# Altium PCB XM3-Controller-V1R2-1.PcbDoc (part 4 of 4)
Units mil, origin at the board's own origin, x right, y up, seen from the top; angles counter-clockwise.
Board outline 10629.92 x 4173.11 mil, 6 copper layers (TOP, GND1, LAYER3, PWR, GND2, BOTTOM), stack 62 mil thick; 362 components, 276 nets, 1145 pads, 503 vias.
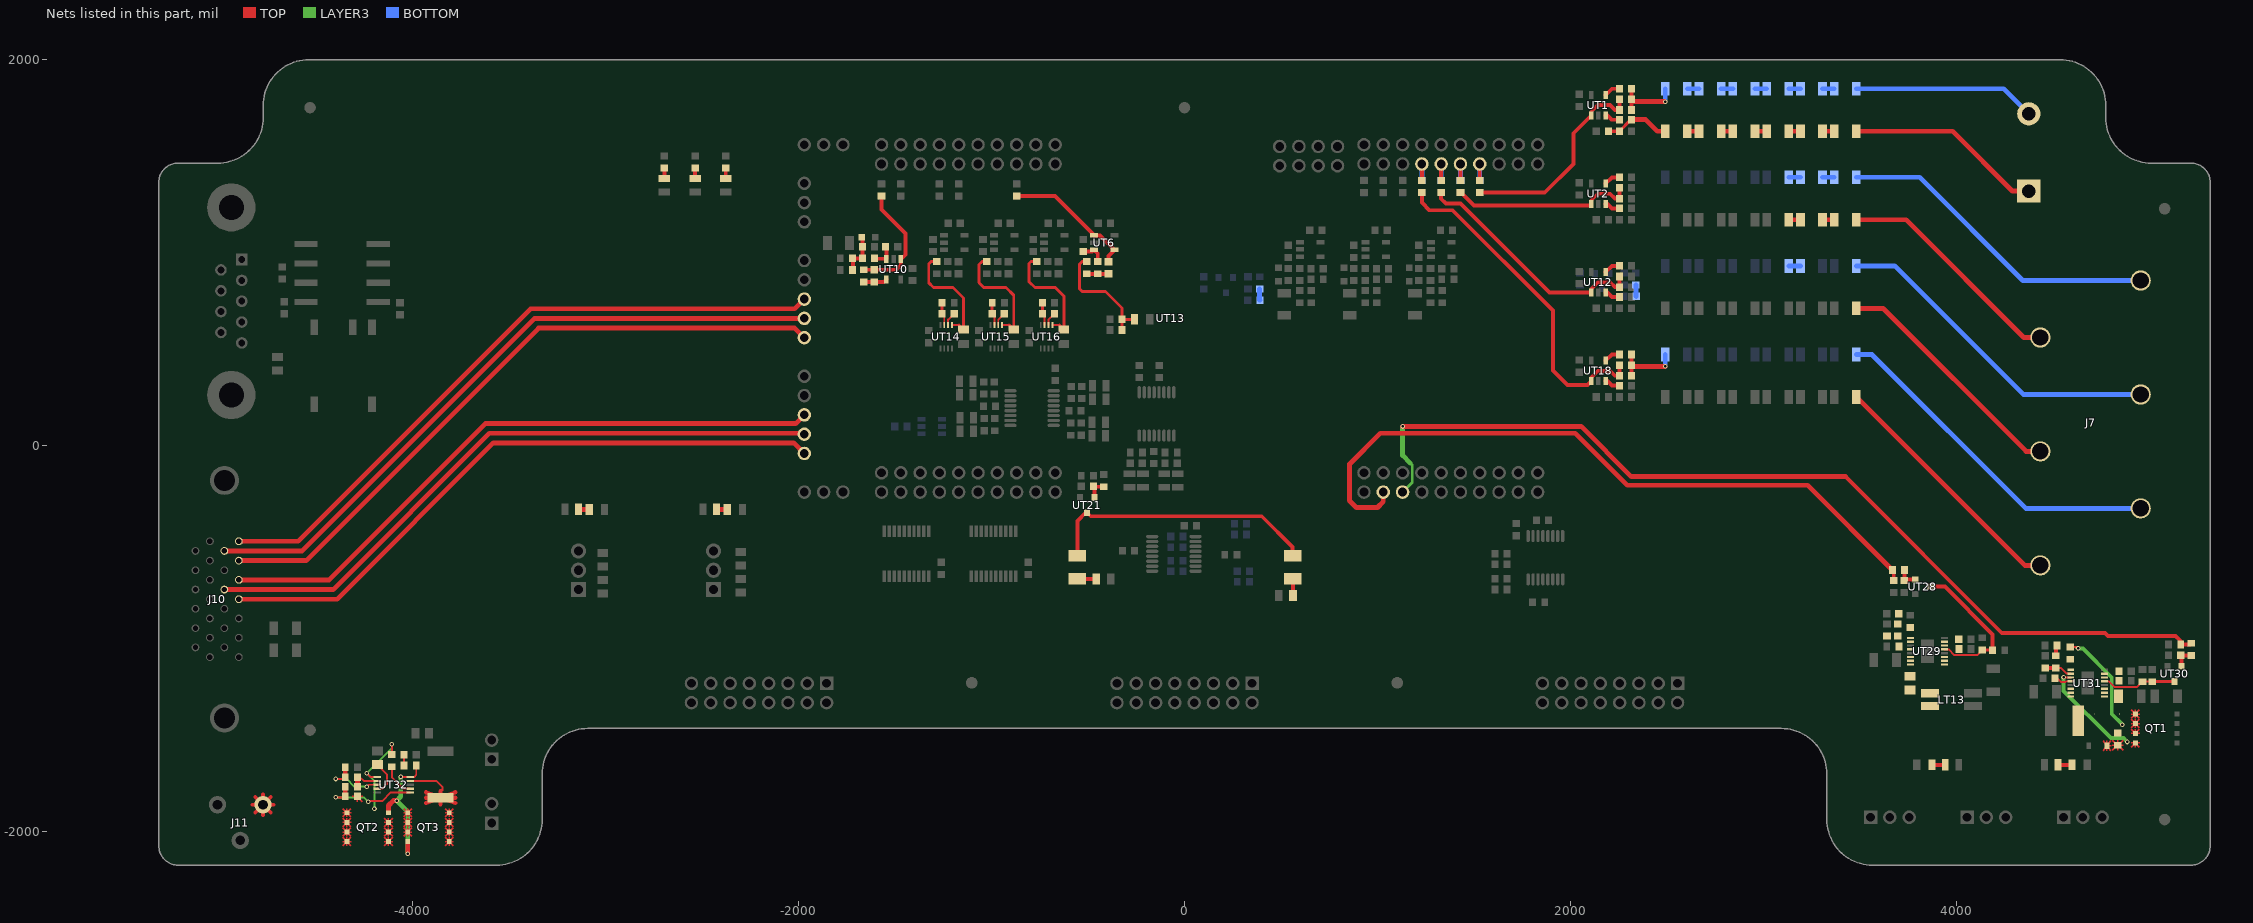
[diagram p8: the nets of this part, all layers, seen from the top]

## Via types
v1: diameter 24, hole 13, TOP to BOTTOM, 503 vias

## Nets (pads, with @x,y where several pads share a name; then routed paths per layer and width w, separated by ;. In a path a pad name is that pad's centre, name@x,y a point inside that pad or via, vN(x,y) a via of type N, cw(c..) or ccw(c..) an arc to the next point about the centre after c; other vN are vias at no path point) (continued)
N51250: RB14.2 RB15.1 | length 60.8
  BOTTOM w25: RB15.1@3130.68,931.88 RB14.2@3191.5,931.88
N51378: RT34.1 RT35.2 | length 60.8
  TOP w25: RT34.1@3305.68,1170.94 RT35.2@3366.5,1170.94
N51382: RT33.1 RT34.2 | length 60.8
  TOP w25: RT33.1@3130.68,1170.94 RT34.2@3191.5,1170.94
N51422: RB7.2 RB8.1 | length 60.8
  BOTTOM w25: RB8.1@3305.68,1390.94 RB7.2@3366.5,1390.94
N51426: RB8.2 RB9.1 | length 60.8
  BOTTOM w25: RB9.1@3130.68,1390.94 RB8.2@3191.5,1390.94
N62914: CT14.1 RT37.2 RT38.2 RT39.1 RT49.2 | length 226.3
  TOP w20: RT49.2@-1721,910.64 -1717.5,914.14 -1717.5,967.14 RT38.2@-1721,970.64 RT39.1@-1669,970.64 RT37.2@-1669,1030.64 -1669,1077.14 CT14.1@-1672.5,1080.64
N63160: CT19.1 RT39.2 UT10.3 | length 125.4
  TOP w20: RT39.2@-1606,970.64 -1604.15,968.79 UT10.3@-1544.9,968.79 -1544.9,1026.54 CT19.1@-1549,1030.64
N63220: CT34.2 RT23.1 RT57.2 UT10.1 | length 625.9
  TOP w20: RT57.2@-1662.5,912.14 CT34.2@-1607.5,912.14 -1491.48,912.14 -1470.1,933.52 UT10.1@-1470.1,968.79 -1466.21,968.79 -1445,990 -1445,1100 -1570,1225 RT23.1@-1570,1293.72
N63260: CT34.1 RT57.1 UT10.4 | length 123.1
  TOP w20: RT57.1@-1662.5,849.14 CT34.1@-1607.5,849.14 -1558.25,849.14 UT10.4@-1544.9,862.49
N66752: CT51.2 RT18.1 RT88.2 UT18.1 | length 1755.3
  TOP w20: RT18.1@1230,1312 1230,1260 1270,1220 1390,1220 1910,700 1910,390 1985,315 2087.93,315 UT18.1@2107.6,334.67 2107.6,353.8 2141.62,387.82 2205,387.82 2230,362.82 CT51.2@2253.5,362.82 RT88.2@2253.5,417.82
N66907: CT51.1 RB26.2 RT87.1 RT88.1 | length 348.9
  TOP w20: CT51.1@2316.5,362.82 RT88.1@2316.5,417.82 RT87.1@2316.5,472.82
  TOP w25: RT88.1@2316.5,417.82 2322.82,411.5 v1(2491.5,411.5)
  BOTTOM w25: v1(2491.5,411.5) RB26.2@2491.5,472.82
N66989: RT87.2 UT18.4 | length 84.3
  TOP w20: UT18.4@2182.4,440.97 2214.25,472.82 RT87.2@2253.5,472.82
N67029: RT90.2 UT18.3 | length 80.6
  TOP w20: UT18.3@2182.4,334.67 2193.14,334.67 2216.05,311.76 RT90.2@2253.5,311.76
N74358: RT68.2 UT12.3 | length 80.6
  TOP w20: UT12.3@2182.4,793.73 2193.14,793.73 2216.05,770.82 RT68.2@2253.5,770.82
N74448: CT36.2 RT19.1 RT58.2 UT12.1 | length 1255.5
  TOP w20: RT19.1@1330,1312 1330,1280 1355,1255 1430,1255 1891.27,793.73 UT12.1@2107.6,793.73 2107.6,812.86 2141.62,846.88 2205,846.88 2230,821.88 CT36.2@2253.5,821.88 RT58.2@2253.5,876.88
N74460: RT40.2 UT12.4 | length 84.3
  TOP w20: UT12.4@2182.4,900.03 2214.25,931.88 RT40.2@2253.5,931.88
N75234: RT28.2 UT2.3 | length 80.6
  TOP w20: UT2.3@2182.4,1252.79 2193.14,1252.79 2216.05,1229.88 RT28.2@2253.5,1229.88
N75324: CT5.2 RT20.1 RT22.2 UT2.1 | length 953.1
  TOP w20: RT20.1@1430,1312 1433,1312 1500,1245 2099.81,1245 UT2.1@2107.6,1252.79 2107.6,1271.92 2141.62,1305.94 2205,1305.94 2230,1280.94 CT5.2@2253.5,1280.94 RT22.2@2253.5,1335.94
N75336: RT14.2 UT2.4 | length 84.3
  TOP w20: UT2.4@2182.4,1359.09 2214.25,1390.94 RT14.2@2253.5,1390.94
N76078: CT3.2 RT3.1 RT4.2 RT5.2 | length 344.7
  TOP w15: RT4.2@2253.5,1630 2312.44,1688.94 RT3.1@2316.5,1688.94
  TOP w20: CT3.2@2196.5,1630 RT4.2@2253.5,1630
  TOP w25: RT3.1@2316.5,1688.94 2317.56,1690 2390,1690 2450,1630 RT5.2@2491.5,1630
N76134: RT3.2 UT1.3 | length 80.6
  TOP w20: UT1.3@2182.4,1711.85 2193.14,1711.85 2216.05,1688.94 RT3.2@2253.5,1688.94
N76224: CT2.2 RT2.2 RT21.1 UT1.1 | length 1081
  TOP w20: RT21.1@1530,1312 1866.99,1312 2015,1460.01 2015,1619.25 UT1.1@2107.6,1711.85 2107.6,1730.98 2141.62,1765 2205,1765 2230,1740 CT2.2@2253.5,1740 RT2.2@2253.5,1795
N76236: RT1.2 UT1.4 | length 84.3
  TOP w20: UT1.4@2182.4,1818.15 2214.25,1850 RT1.2@2253.5,1850
N76260: CT2.1 RB6.2 RT1.1 RT2.1 | length 356.3
  TOP w20: CT2.1@2316.5,1740 RT2.1@2316.5,1795 RT1.1@2316.5,1850
  TOP w25: RT2.1@2316.5,1795 2328,1783.5 v1(2491.5,1783.5)
  BOTTOM w25: v1(2491.5,1783.5) RB6.2@2491.5,1850
N78650: CT26.1 RT47.2 RT48.1 | length 111.9
  TOP w20: RT47.2@-505.61,890.9 RT48.1@-449.67,890.9 CT26.1@-393.73,890.9
N78658: CT26.2 RT27.1 UT6.1 UT6.4 | length 698.1
  TOP w20: RT27.1@-870,1293.72 -670.91,1293.72 -468.76,1091.57 UT6.1@-468.76,1089.8 -437.26,1089.8 UT6.4@-362.46,1015 -393.73,983.73 CT26.2@-393.73,953.9
N78724: CT18.2 RT48.2 UT6.3 | length 129.6
  TOP w20: CT18.2@-525.61,1005.9 -477.86,1005.9 UT6.3@-468.76,1015 -449.67,995.91 RT48.2@-449.67,953.9
N79088: CT43.2 RT47.1 RT82.2 RT83.1 | length 612.2
  TOP w15: RT47.1@-505.61,953.9 -506.71,955 -530,955 -545,940 -545,815 -530,800 -410,800 -323.5,713.5 RT82.2@-323.5,655 ; CT43.2@-323.5,600 RT82.2@-323.5,655 ; RT83.1@-259.37,655 RT82.2@-323.5,655
N88263: DT5.1 RT110.2 | length 55.6
  TOP w25: DT5.1@-2425,-330 RT110.2@-2369.37,-330
N88433: DT4.1 RT109.2 | length 55.6
  TOP w25: DT4.1@-3140,-330 RT109.2@-3084.37,-330
N88603: DT12.1 RT138.2 | length 73
  TOP w20: DT12.1@4526,-1653.47 RT138.2@4599.01,-1653.47
N88777: DT11.1 RT137.2 | length 68.4
  TOP w20: RT137.2@3873.59,-1653.47 DT11.1@3942,-1653.47
N93191: DT1.1 RT11.2 | length 53.5
  TOP w20: DT1.1@-2695,1385 RT11.2@-2695,1438.5
N93195: DT3.1 RT13.2 | length 53.5
  TOP w20: DT3.1@-2376.88,1385 RT13.2@-2376.88,1438.5
N93199: DT2.1 RT12.2 | length 53.5
  TOP w20: DT2.1@-2535.94,1385 RT12.2@-2535.94,1438.5
N95779: RT123.1 RT128.1 UT28.3 UT29.13 | length 779.1
  TOP w10: UT29.13@3938,-1055.15 3958.9,-1055.15 3988.44,-1084.69 4106.81,-1084.69 RT123.1@4134,-1057.5
  TOP w15: RT123.1@4134,-1057.5 4186,-1057.5 RT128.1@4187.5,-1059
  TOP w20: UT28.3@3866,-730 3940.01,-730 4187.5,-977.49 RT128.1@4187.5,-1059
N96795: RT131.1 RT132.1 UT30.3 UT31.13 | length 386.1
  TOP w10: UT31.13@4768,-1220.15 4788.9,-1220.15 4818.44,-1249.69 4936.81,-1249.69 RT131.1@4964,-1222.5 RT132.1@5014,-1222.5
  TOP w15: RT132.1@5014,-1222.5 5128.5,-1222.5 UT30.3@5130,-1221
N97055: CT84.1 DT9.1 QT1.1 QT1.2 QT1.3 RT129.2 RT135.1 | length 1089.1
  TOP w7: 4905.9,-1490 QT1.3@4927.32,-1490 ; 4905.9,-1440 QT1.2@4927.32,-1440 ; 4905.9,-1390 QT1.1@4927.32,-1390 ; 4906.17,-1468.18 QT1.3@4927.32,-1490 ; 4906.17,-1461.82 QT1.2@4927.32,-1440 ; 4906.17,-1418.18 QT1.2@4927.32,-1440 ; 4906.17,-1411.82 QT1.1@4927.32,-1390 ; 4906.17,-1368.18 QT1.1@4927.32,-1390 ; 4927.32,-1468.18 QT1.3@4927.32,-1490 ; 4927.32,-1461.82 QT1.2@4927.32,-1440 ; 4927.32,-1418.18 QT1.2@4927.32,-1440 ; 4927.32,-1411.82 QT1.1@4927.32,-1390 ; 4927.32,-1368.18 QT1.1@4927.32,-1390 ; 4948.47,-1468.18 QT1.3@4927.32,-1490 ; 4948.47,-1461.82 QT1.2@4927.32,-1440 ; 4948.47,-1418.18 QT1.2@4927.32,-1440 ; 4948.47,-1411.82 QT1.1@4927.32,-1390 ; 4948.47,-1368.18 QT1.1@4927.32,-1390 ; 4948.74,-1490 QT1.3@4927.32,-1490 ; 4948.74,-1440 QT1.2@4927.32,-1440 ; 4948.74,-1390 QT1.1@4927.32,-1390
  TOP w10: RT129.2@4590,-1043.5 4623.5,-1043.5 v1(4630,-1050)
  LAYER3 w20: v1(4630,-1050) 4655,-1050 4805,-1200 4805,-1390 v1(4860,-1445)
N97211: CT79.2 RT130.1 UT31.2 | length 144.1
  TOP w10: RT130.1@4515,-1151.5 4541.5,-1151.5 4570.75,-1180.75 UT31.2@4592,-1180.75
  TOP w20: CT79.2@4460,-1151.5 RT130.1@4515,-1151.5
N97283: CT75.1 RT130.2 | length 56.2
  TOP w20: RT130.2@4515,-1088.5 4515,-1041.5 CT75.1@4521.5,-1035
N139937: RT9.1 RT10.2 | length 60.8
  TOP w25: RT9.1@3305.68,1630 RT10.2@3366.5,1630
N139941: RT8.1 RT9.2 | length 60.8
  TOP w25: RT8.1@3130.68,1630 RT9.2@3191.5,1630
N139945: RT7.1 RT8.2 | length 60.8
  TOP w25: RT7.1@2955.68,1630 RT8.2@3016.5,1630
N139949: RT6.1 RT7.2 | length 60.8
  TOP w25: RT6.1@2780.68,1630 RT7.2@2841.5,1630
N139953: RT5.1 RT6.2 | length 60.8
  TOP w25: RT5.1@2605.68,1630 RT6.2@2666.5,1630
N140053: RB1.2 RB2.1 | length 60.8
  BOTTOM w25: RB2.1@3305.68,1850 RB1.2@3366.5,1850
N140057: RB2.2 RB3.1 | length 60.8
  BOTTOM w25: RB3.1@3130.68,1850 RB2.2@3191.5,1850
N140061: RB3.2 RB4.1 | length 60.8
  BOTTOM w25: RB4.1@2955.68,1850 RB3.2@3016.5,1850
N140065: RB4.2 RB5.1 | length 60.8
  BOTTOM w25: RB5.1@2780.68,1850 RB4.2@2841.5,1850
N140069: RB5.2 RB6.1 | length 60.8
  BOTTOM w25: RB6.1@2605.68,1850 RB5.2@2666.5,1850
N141814: CB17.1 RB19.2 | length 59.1
  BOTTOM w25: RB19.2@2339.25,832.67 2339.25,775.67 CB17.1@2340.75,774.17
N143941: CB18.1 RB20.2 | length 59.1
  BOTTOM w25: RB20.2@389.25,812.66 389.25,755.66 CB18.1@390.75,754.16
N145779: CT69.1 RT115.2 UT28.1 | length 110.9
  TOP w20: CT69.1@3730.01,-697.5 CT69.1@3731.5,-696.01 ; RT115.2@3731.5,-643.99 CT69.1@3731.5,-696.01 ; UT28.1@3787,-693 3734.51,-693 CT69.1@3731.5,-696.01
N146352: CT77.1 RT127.2 UT30.1 | length 110.9
  TOP w20: CT77.1@5162.5,-1085.01 CT77.1@5163.99,-1086.5 ; UT30.1@5167,-1142 5167,-1089.51 CT77.1@5163.99,-1086.5 ; RT127.2@5216.01,-1086.5 CT77.1@5163.99,-1086.5
N147166: QT2.1 QT2.2 QT2.3 QT3.1 QT3.2 QT3.3 | length 1248.2
  TOP w7: -4146.24,-2051.67 QT2.1@-4124.82,-2051.67 ; -4146.24,-2001.67 QT2.2@-4124.82,-2001.67 ; -4146.24,-1951.67 QT2.3@-4124.82,-1951.67 ; -4145.97,-2073.49 QT2.1@-4124.82,-2051.67 ; -4145.97,-2029.85 QT2.1@-4124.82,-2051.67 ; -4145.97,-2023.49 QT2.2@-4124.82,-2001.67 ; -4145.97,-1979.85 QT2.2@-4124.82,-2001.67 ; -4145.97,-1973.49 QT2.3@-4124.82,-1951.67 ; -4145.97,-1929.85 QT2.3@-4124.82,-1951.67 ; -4124.82,-2073.49 QT2.1@-4124.82,-2051.67 ; -4124.82,-2029.85 QT2.1@-4124.82,-2051.67 ; -4124.82,-2023.49 QT2.2@-4124.82,-2001.67 ; -4124.82,-1979.85 QT2.2@-4124.82,-2001.67 ; -4124.82,-1973.49 QT2.3@-4124.82,-1951.67 ; -4124.82,-1929.85 QT2.3@-4124.82,-1951.67 ; -4103.67,-2073.49 QT2.1@-4124.82,-2051.67 ; -4103.67,-2029.85 QT2.1@-4124.82,-2051.67 ; -4103.67,-2023.49 QT2.2@-4124.82,-2001.67 ; -4103.67,-1979.85 QT2.2@-4124.82,-2001.67 ; -4103.67,-1973.49 QT2.3@-4124.82,-1951.67 ; -4103.67,-1929.85 QT2.3@-4124.82,-1951.67 ; -4103.4,-2051.67 QT2.1@-4124.82,-2051.67 ; -4103.4,-2001.67 QT2.2@-4124.82,-2001.67 ; -4103.4,-1951.67 QT2.3@-4124.82,-1951.67 ; -4046.6,-2001.67 QT3.3@-4025.18,-2001.67 ; -4046.6,-1951.67 QT3.2@-4025.18,-1951.67 ; -4046.6,-1901.67 QT3.1@-4025.18,-1901.67 ; -4046.33,-2023.49 QT3.3@-4025.18,-2001.67 ; -4046.33,-1979.85 QT3.3@-4025.18,-2001.67 ; -4046.33,-1973.49 QT3.2@-4025.18,-1951.67 ; -4046.33,-1929.85 QT3.2@-4025.18,-1951.67 ; -4046.33,-1923.49 QT3.1@-4025.18,-1901.67 ; -4046.33,-1879.85 QT3.1@-4025.18,-1901.67 ; -4025.18,-2023.49 QT3.3@-4025.18,-2001.67 ; -4025.18,-1979.85 QT3.3@-4025.18,-2001.67 ; -4025.18,-1973.49 QT3.2@-4025.18,-1951.67 ; -4025.18,-1929.85 QT3.2@-4025.18,-1951.67 ; -4025.18,-1923.49 QT3.1@-4025.18,-1901.67 ; -4025.18,-1879.85 QT3.1@-4025.18,-1901.67 ; -4004.03,-2023.49 QT3.3@-4025.18,-2001.67 ; -4004.03,-1979.85 QT3.3@-4025.18,-2001.67 ; -4004.03,-1973.49 QT3.2@-4025.18,-1951.67 ; -4004.03,-1929.85 QT3.2@-4025.18,-1951.67 ; -4004.03,-1923.49 QT3.1@-4025.18,-1901.67 ; -4004.03,-1879.85 QT3.1@-4025.18,-1901.67 ; -4003.76,-2001.67 QT3.3@-4025.18,-2001.67 ; -4003.76,-1951.67 QT3.2@-4025.18,-1951.67 ; -4003.76,-1901.67 QT3.1@-4025.18,-1901.67
N148075: QT2.4 QT3.4 RT139.2 UT32.10 | length 715.5
  TOP w10: v1(-4060.96,-1715.98) -4013.19,-1715.98 UT32.10@-4012.5,-1716.67 -3992.5,-1716.67 -3981,-1705.17 RT139.2@-3981,-1656.67
  TOP w25: QT2.4@-4124.82,-1901.67 -4124.82,-1863.99 -4099.82,-1838.99 v1(-4082.5,-1838.99) ; v1(-4025.18,-2113.33) QT3.4@-4025.18,-2051.67
  LAYER3 w25: v1(-4060.96,-1715.98) -4060.96,-1817.45 v1(-4082.5,-1838.99) -4025.18,-1896.31 v1(-4025.18,-2113.33)
N148197: CT87.1 RT139.1 | length 55
  TOP w10: RT139.1@-4044,-1656.67 CT87.1@-4044,-1601.67
N148540: QT3.5 QT3.6 QT3.7 QT3.8 RT141.1 UT32.9 | length 1572.6
  TOP w7: -3831.24,-2051.67 QT3.5@-3809.82,-2051.67 ; -3831.24,-2001.67 QT3.6@-3809.82,-2001.67 ; -3831.24,-1951.67 QT3.7@-3809.82,-1951.67 ; -3831.24,-1901.67 QT3.8@-3809.82,-1901.67 ; -3830.97,-2073.49 QT3.5@-3809.82,-2051.67 ; -3830.97,-2029.85 QT3.5@-3809.82,-2051.67 ; -3830.97,-2023.49 QT3.6@-3809.82,-2001.67 ; -3830.97,-1979.85 QT3.6@-3809.82,-2001.67 ; -3830.97,-1973.49 QT3.7@-3809.82,-1951.67 ; -3830.97,-1929.85 QT3.7@-3809.82,-1951.67 ; -3830.97,-1923.49 QT3.8@-3809.82,-1901.67 ; -3830.97,-1879.85 QT3.8@-3809.82,-1901.67 ; -3809.82,-2073.49 QT3.5@-3809.82,-2051.67 ; -3809.82,-2029.85 QT3.5@-3809.82,-2051.67 ; -3809.82,-2023.49 QT3.6@-3809.82,-2001.67 ; -3809.82,-1979.85 QT3.6@-3809.82,-2001.67 ; -3809.82,-1973.49 QT3.7@-3809.82,-1951.67 ; -3809.82,-1929.85 QT3.7@-3809.82,-1951.67 ; -3809.82,-1923.49 QT3.8@-3809.82,-1901.67 ; -3809.82,-1879.85 QT3.8@-3809.82,-1901.67 ; -3788.67,-2073.49 QT3.5@-3809.82,-2051.67 ; -3788.67,-2029.85 QT3.5@-3809.82,-2051.67 ; -3788.67,-2023.49 QT3.6@-3809.82,-2001.67 ; -3788.67,-1979.85 QT3.6@-3809.82,-2001.67 ; -3788.67,-1973.49 QT3.7@-3809.82,-1951.67 ; -3788.67,-1929.85 QT3.7@-3809.82,-1951.67 ; -3788.67,-1923.49 QT3.8@-3809.82,-1901.67 ; -3788.67,-1879.85 QT3.8@-3809.82,-1901.67 ; -3788.4,-2051.67 QT3.5@-3809.82,-2051.67 ; -3788.4,-2001.67 QT3.6@-3809.82,-2001.67 ; -3788.4,-1951.67 QT3.7@-3809.82,-1951.67 ; -3788.4,-1901.67 QT3.8@-3809.82,-1901.67
  TOP w10: UT32.9@-4012.5,-1736.67 -3876.66,-1736.67 -3844.58,-1768.75 -3844.58,-1784.58 -3845,-1785
  TOP w22: -3930.95,-1851.34 RT141.1@-3855,-1823.41 ; -3930.95,-1823.41 RT141.1@-3855,-1823.41 ; -3930.95,-1795.48 RT141.1@-3855,-1823.41 ; -3855,-1857.04 RT141.1@-3855,-1823.41 ; -3855,-1789.78 RT141.1@-3855,-1823.41 ; -3779.05,-1851.34 RT141.1@-3855,-1823.41 ; -3779.05,-1823.41 RT141.1@-3855,-1823.41 ; -3779.05,-1795.48 RT141.1@-3855,-1823.41
N149103: RT143.1 RT144.2 UT32.6 | length 514.9
  TOP w10: v1(-4397.5,-1821.67) -4354,-1821.67 RT144.2@-4349,-1816.67 ; v1(-4229.58,-1844.59) -4226.66,-1841.67 -4157.5,-1841.67 -4112.5,-1796.67 UT32.6@-4012.5,-1796.67
  TOP w25: RT144.2@-4349,-1816.67 RT143.1@-4349,-1766.67
  LAYER3 w10: v1(-4397.5,-1821.67) -4252.5,-1821.67 v1(-4229.58,-1844.59)
N149107: RT142.1 RT143.2 UT32.2 | length 161.8
  TOP w10: RT142.1@-4286,-1716.67 -4272.5,-1716.67 -4252.5,-1736.67 UT32.2@-4182.5,-1736.67
  TOP w25: RT143.2@-4286,-1766.67 RT142.1@-4286,-1716.67
N149113: RT140.1 RT142.2 UT32.3 | length 338.4
  TOP w10: v1(-4397.5,-1726.67) -4359,-1726.67 RT142.2@-4349,-1716.67 ; v1(-4237.5,-1766.67) -4227.5,-1756.67 UT32.3@-4182.5,-1756.67
  TOP w25: RT142.2@-4349,-1716.67 RT140.1@-4349,-1666.67
  LAYER3 w10: v1(-4397.5,-1726.67) -4341.66,-1726.67 -4301.66,-1766.67 v1(-4237.5,-1766.67)
N149983: CT88.1 UT32.4 | length 180.6
  TOP w10: UT32.4@-4182.5,-1776.67 -4157.5,-1776.67 -4132.5,-1751.67 -4132.5,-1702.1 CT88.1@-4182.5,-1652.1
N150621: RT136.2 UT32.7 | length 173.4
  TOP w10: RT136.2@-4107.5,-1663.17 -4107.5,-1716.67 -4047.5,-1776.67 UT32.7@-4012.5,-1776.67
N177905: DT7.1 RT119.2 | length 86
  TOP w20: DT7.1@560,-690 562.4,-692.4 RT119.2@562.4,-775
N177925: DT6.2 DT7.2 UT21.3 | length 1431.9
  TOP w20: DT6.2@-555,-570 -555,-389.6 -512.24,-346.84 UT21.3@-504.29,-346.84 -486.13,-365 400,-365 560,-525 DT7.2@560,-570
N178332: DT6.1 RT116.2 | length 97.6
  TOP w20: DT6.1@-555,-690 RT116.2@-457.4,-690
N179044: CT59.1 RT108.2 UT21.1 | length 110.9
  TOP w20: CT59.1@-471.79,-210.85 CT59.1@-470.3,-212.34 ; UT21.1@-467.29,-267.84 -467.29,-215.35 CT59.1@-470.3,-212.34 ; RT108.2@-418.28,-212.34 CT59.1@-470.3,-212.34
N200782: RT134.2 UT31.14
N203219: RT133.2 UT31.4 | length 89.8
  TOP w10: RT133.2@4511.5,-1205 4521.5,-1205 4540.34,-1223.84 4566.17,-1223.84 4569.86,-1220.15 UT31.4@4592,-1220.15
N204184: DT9.2 LT14.2 UT31.6 UT31.7 UT31.8 UT31.9 UT31.10 UT31.11
N204300: RT129.1 UT31.1
N204715: CT80.2 UT31.15
N205443: DT10.C QT1.4 RT135.2 UT31.3 | length 1138.7
  TOP w7: 4760.66,-1580.52 DT10.C@4780,-1555 ; 4760.66,-1529.48 DT10.C@4780,-1555 ; 4780,-1580.52 DT10.C@4780,-1555 ; 4780,-1529.48 DT10.C@4780,-1555 ; 4799.34,-1580.52 DT10.C@4780,-1555 ; 4799.34,-1529.48 DT10.C@4780,-1555 ; 4801.52,-1555 DT10.C@4780,-1555 ; 4806.29,-1577.34 RT135.2@4835,-1551.5 ; 4806.29,-1551.5 RT135.2@4835,-1551.5 ; 4806.29,-1525.66 RT135.2@4835,-1551.5 ; 4835,-1578.24 RT135.2@4835,-1551.5 ; 4835,-1524.76 RT135.2@4835,-1551.5 ; 4863.71,-1577.34 RT135.2@4835,-1551.5 ; 4863.71,-1551.5 RT135.2@4835,-1551.5 ; 4863.71,-1525.66 RT135.2@4835,-1551.5 ; 4905.9,-1540 QT1.4@4927.32,-1540 ; 4906.17,-1561.82 QT1.4@4927.32,-1540 ; 4927.32,-1561.82 QT1.4@4927.32,-1540 ; 4948.47,-1561.82 QT1.4@4927.32,-1540 ; 4948.74,-1540 QT1.4@4927.32,-1540
  TOP w10: v1(4555,-1199.84) 4560,-1199.84 4560.16,-1200 4570,-1200 4570.45,-1200.45 UT31.3@4592,-1200.45
  LAYER3 w20: v1(4555,-1199.84) 4555,-1270 4800,-1515 4865,-1515 v1(4885,-1535)
N208883: CT82.1 LT13.3 UT29.6 UT29.7 UT29.8 UT29.9 UT29.10 UT29.11
N209249: RT121.1 UT29.1
N209309: RT125.2 UT29.4
N209373: RT126.2 UT29.14
N209381: CT73.2 RT122.1 UT29.2
N209421: CT74.2 UT29.15
N209493: CT71.1 RT122.2
N213371: CT82.2 DT8.2 LT13.4
N273504: RT41.1 RT84.2 UT14.5 | length 594.5
  TOP w10: UT14.5@-1205,626 -1168.6,626
  TOP w15: RT41.1@-1283.15,953.9 -1313.44,953.9 -1325,942.34 -1325,845 -1300,820 -1200,820 -1145,765 RT84.2@-1145,602.4 ; -1168.6,626 RT84.2@-1145,602.4 ; RT84.2@-1145,597.4 RT84.2@-1145,602.4
N273798: CT40.2 UT14.6 | length 72
  TOP w10: UT14.6@-1225,626 -1225,653.5 CT40.2@-1193.5,685
N273802: CT40.1 RT69.2 UT14.7 | length 118.8
  TOP w10: CT40.1@-1256.5,685 -1245,673.5 UT14.7@-1245,626
  TOP w15: CT40.1@-1256.5,685 RT69.2@-1256.5,740
N275299: RT43.1 RT85.2 UT15.5 | length 595.4
  TOP w10: UT15.5@-945,626 -908.6,626
  TOP w15: RT43.1@-1023.97,953.9 -1050,953.9 -1065,938.9 -1065,845 -1040,820 -925,820 -885,780 RT85.2@-885,602.4 -908.6,626
N275399: CT41.1 RT70.2 UT15.7 | length 118.8
  TOP w10: CT41.1@-996.5,685 -985,673.5 UT15.7@-985,626
  TOP w15: CT41.1@-996.5,685 RT70.2@-996.5,740
N275407: CT41.2 UT15.6 | length 72
  TOP w10: UT15.6@-965,626 -965,653.5 CT41.2@-933.5,685
N275841: RT45.1 RT86.2 UT16.5 | length 592.3
  TOP w10: UT16.5@-685,626 -648.6,626
  TOP w15: RT45.1@-764.79,953.9 -765.48,954.59 -794.39,954.59 -805,943.98 -805,850 -775,820 -670,820 -625,775 RT86.2@-625,602.4 -648.6,626
N275941: CT42.1 RT71.2 UT16.7 | length 118.8
  TOP w10: CT42.1@-736.5,685 -725,673.5 UT16.7@-725,626
  TOP w15: CT42.1@-736.5,685 RT71.2@-736.5,740
N275949: CT42.2 UT16.6 | length 72
  TOP w10: UT16.6@-705,626 -705,653.5 CT42.2@-673.5,685
QEA_A: J10.14 UT13.89 | length 3288.3
  TOP w25: J10.14@-4900,-795 -4390.8,-795 -3580.8,15 -2025,15 UT13.89@-1970,-40
QEA_B: J10.16 UT13.90 | length 3342.6
  TOP w7: UT13.90@-1975,65 UT13.90@-1970,60
  TOP w25: J10.16@-4975,-745 -4411.52,-745 -3601.52,65 UT13.90@-1975,65
QEA_I: J10.18 UT13.91 | length 3284.2
  TOP w25: J10.18@-4900,-695 -4432.24,-695 -3622.24,115 -2015,115 UT13.91@-1970,160
QEB_A: J10.22 UT13.94 | length 3449.8
  TOP w25: J10.22@-4900,-595 -4551.9,-595 -3346.9,610 -2020,610 UT13.94@-1970,560
QEB_B: J10.24 UT13.95 | length 3504.1
  TOP w25: J10.24@-4975,-545 -4572.62,-545 -3367.62,660 UT13.95@-1970,660
QEB_I: J10.26 UT13.96 | length 3449.8
  TOP w25: J10.26@-4900,-495 -4593.34,-495 -3388.34,710 -2020,710 UT13.96@-1970,760
SHUTDOWN+15V: RT124.1 RT127.1 UT13.13 | length 4948.4
  TOP w20: 3425,-160 4235,-970 4770,-970 4785,-985 5135,-985 5162.5,-1012.5 RT124.1@5162.5,-1030 5209.51,-1030 RT127.1@5216.01,-1023.5
  TOP w25: v1(1130,100) 2055,100 2315,-160 3425,-160
  LAYER3 w15: UT13.13@1130,-240 1180,-190 1180,-100 1170,-90
  LAYER3 w25: v1(1130,100) 1130,-50 1170,-90
SHUTDOWN-15V: RT115.1 RT117.1 UT13.12 | length 3671.6
  TOP w20: RT115.1@3668.5,-643.99 3675,-650.49 RT117.1@3675,-697.5
  TOP w25: UT13.12@1030,-240 1030,-290 1000,-320 890,-320 855,-285 855,-95 1015,65 2025,65 2295,-205 3229.51,-205 RT115.1@3668.5,-643.99
VA-M: J7.2 RB21.1 | length 1804.4
  BOTTOM w25: RB21.1@3480.68,472.82 3562.19,472.82 4359.73,-324.72 J7.2@4954.69,-324.72
VA-P: J7.1 RT99.1 | length 1315.9
  TOP w25: RT99.1@3480.68,252.82 4353.5,-620 J7.1@4435,-620
VB-M: J7.4 RB13.1 | length 1749.9
  BOTTOM w25: RB13.1@3480.68,931.88 3679.97,931.88 4346.02,265.83 J7.4@4954.69,265.83
VB-P: J7.3 RT81.1 | length 1261.4
  TOP w25: RT81.1@3480.68,711.88 3619.41,711.88 4360.74,-29.45 J7.3@4435,-29.45
VC-M: J7.6 RB7.1 | length 1695.4
  BOTTOM w25: RB7.1@3480.68,1390.94 3809.05,1390.94 4343.61,856.38 J7.6@4954.69,856.38
VC-P: J7.5 RT35.1 | length 1206.9
  TOP w25: RT35.1@3480.68,1170.94 3739.06,1170.94 4348.9,561.1 J7.5@4435,561.1
VDC-M: J8.2 RB1.1 | length 948.2
  BOTTOM w25: RB1.1@3480.68,1850 4245,1850 J8.2@4375,1720
VDC-P: J8.1 RT10.1 | length 1022.7
  TOP w25: RT10.1@3480.68,1630 3980,1630 4290,1320 J8.1@4375,1320
VIN: J11.1 QT2.5 QT2.6 QT2.7 QT2.8 RT136.1 RT144.1 UT32.1 | length 1918.6
  TOP w7: -4361.6,-2051.67 QT2.8@-4340.18,-2051.67 ; -4361.6,-2001.67 QT2.7@-4340.18,-2001.67 ; -4361.6,-1951.67 QT2.6@-4340.18,-1951.67 ; -4361.6,-1901.67 QT2.5@-4340.18,-1901.67 ; -4361.33,-2073.49 QT2.8@-4340.18,-2051.67 ; -4361.33,-2029.85 QT2.8@-4340.18,-2051.67 ; -4361.33,-2023.49 QT2.7@-4340.18,-2001.67 ; -4361.33,-1979.85 QT2.7@-4340.18,-2001.67 ; -4361.33,-1973.49 QT2.6@-4340.18,-1951.67 ; -4361.33,-1929.85 QT2.6@-4340.18,-1951.67 ; -4361.33,-1923.49 QT2.5@-4340.18,-1901.67 ; -4361.33,-1879.85 QT2.5@-4340.18,-1901.67 ; -4340.18,-2073.49 QT2.8@-4340.18,-2051.67 ; -4340.18,-2029.85 QT2.8@-4340.18,-2051.67 ; -4340.18,-2023.49 QT2.7@-4340.18,-2001.67 ; -4340.18,-1979.85 QT2.7@-4340.18,-2001.67 ; -4340.18,-1973.49 QT2.6@-4340.18,-1951.67 ; -4340.18,-1929.85 QT2.6@-4340.18,-1951.67 ; -4340.18,-1923.49 QT2.5@-4340.18,-1901.67 ; -4340.18,-1879.85 QT2.5@-4340.18,-1901.67 ; -4319.03,-2073.49 QT2.8@-4340.18,-2051.67 ; -4319.03,-2029.85 QT2.8@-4340.18,-2051.67 ; -4319.03,-2023.49 QT2.7@-4340.18,-2001.67 ; -4319.03,-1979.85 QT2.7@-4340.18,-2001.67 ; -4319.03,-1973.49 QT2.6@-4340.18,-1951.67 ; -4319.03,-1929.85 QT2.6@-4340.18,-1951.67 ; -4319.03,-1923.49 QT2.5@-4340.18,-1901.67 ; -4319.03,-1879.85 QT2.5@-4340.18,-1901.67 ; -4318.76,-2051.67 QT2.8@-4340.18,-2051.67 ; -4318.76,-2001.67 QT2.7@-4340.18,-2001.67 ; -4318.76,-1951.67 QT2.6@-4340.18,-1951.67 ; -4318.76,-1901.67 QT2.5@-4340.18,-1901.67 ; -4312.74,-1816.67 RT144.1@-4286,-1816.67 ; -4286,-1845.38 RT144.1@-4286,-1816.67 ; -4260.16,-1845.38 RT144.1@-4286,-1816.67 ; -4259.26,-1816.67 RT144.1@-4286,-1816.67
  TOP w10: v1(-4237.5,-1696.67) -4217.5,-1716.67 UT32.1@-4182.5,-1716.67 ; RT136.1@-4107.5,-1600.17 v1(-4107.5,-1546.67)
  TOP w20: -4829.02,-1860 J11.1@-4775,-1860 ; -4815.2,-1900.2 J11.1@-4775,-1860 ; -4815.2,-1819.8 J11.1@-4775,-1860 ; -4775,-1914.02 J11.1@-4775,-1860 ; -4775,-1805.98 J11.1@-4775,-1860 ; -4734.8,-1900.2 J11.1@-4775,-1860 ; -4734.8,-1819.8 J11.1@-4775,-1860 ; -4720.98,-1860 J11.1@-4775,-1860
  LAYER3 w10: v1(-4197.5,-1881.67) -4197.5,-1736.67 v1(-4237.5,-1696.67) -4107.5,-1566.67 v1(-4107.5,-1546.67)
VSENSE-A: CB4.1 RT18.2 UT13.27 | length 170
  TOP w20: RT18.2@1230,1375 UT13.27@1230,1460
  BOTTOM w25: CB4.1@1230,1375 UT13.27@1230,1460
VSENSE-B: CB3.1 RT19.2 UT13.26 | length 170
  TOP w20: RT19.2@1330,1375 UT13.26@1330,1460
  BOTTOM w25: CB3.1@1330,1375 UT13.26@1330,1460
VSENSE-C: CB2.1 RT20.2 UT13.25 | length 170
  TOP w20: RT20.2@1430,1375 UT13.25@1430,1460
  BOTTOM w25: CB2.1@1430,1375 UT13.25@1430,1460
VSENSE-DC: CB1.1 RT21.2 UT13.24 | length 170
  TOP w20: RT21.2@1530,1375 UT13.24@1530,1460
  BOTTOM w25: CB1.1@1530,1375 UT13.24@1530,1460
pads on no net: J9.1 J9.4 J9.6 J9.8 J10. UT13.2 UT13.5 UT13.6 UT13.7 UT13.8 UT13.9 UT13.10 UT13.11 UT13.14 UT13.15 UT13.16 UT13.17 UT13.18 UT13.19 UT13.23 UT13.31 UT13.32 UT13.33 UT13.34 UT13.43 UT13.44 UT13.50 UT13.56 UT13.64 UT13.65 UT13.68 UT13.71 UT13.72 UT13.77 UT13.81 UT13.83 UT13.85 UT13.87 UT17.8 UT20.9 UT20.10 UT20.11 UT20.13 UT20.14 UT20.15 UT22.17 UT22.18 UT23.11 UT23.12 UT23.13 UT23.14 UT23.15 UT25.9 UT25.10 UT25.11 UT25.13 UT25.14 UT25.15 UT29.3 UT29.12 UT31.12

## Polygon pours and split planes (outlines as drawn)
N208883 on TOP "TOP-N208883" (solid, remove dead copper, pour order 18): 3722,-1088 3785,-1088 3785,-1150 3916,-1150 3916,-1088 3962,-1088 3962,-1308 3804,-1308 3804,-1221 3722,-1221
N200782 on TOP "TOP-N200782" (solid, remove dead copper, pour order 2): 4860,-1198 4804,-1198 4800,-1194 4750,-1194 4750,-1206 4790,-1206 4822,-1238 4860,-1238
N204184 on TOP "TOP-N204184" (solid, remove dead copper, pour order 21): 4552,-1253 4615,-1253 4615,-1315 4746,-1315 4746,-1253 4792,-1253 4792,-1515 4595,-1515 4552,-1472
+12V on TOP "TOP-+12V" (solid, remove dead copper, pour order 37): -3945,-1445 -3945,-695 -2630,-695 -2350,-695 -2320,-725 -2245,-725 -2245,-825 -2315,-895 -2790,-895 -2895,-1000 -2895,-1445 -3340,-1445
0 on TOP "TOP-0" (solid, remove dead copper, pour order 9): 3596,-1146 3596,-1070 3488,-1070 3488,-1146
N97055 on TOP "TOP-N97055" (solid, remove dead copper, pour order 16): 4806,-1262 4866,-1262 4866,-1330 4889,-1353 4959,-1353 4959,-1513 4806,-1513
N205443 on TOP "TOP-N205443" (solid, remove dead copper, pour order 13): 4959,-1520 4959,-1585 4756,-1585 4756,-1520
N213371 on TOP "TOP-N213371" (solid, remove dead copper, pour order 14): 3791,-1237 3791,-1320 3921,-1320 3921,-1386 3722,-1386 3722,-1237
+12V on TOP "TOP-+12V 1" (solid, remove dead copper, pour order 24): 4610,-1246 4610,-1234 4495,-1234 4495,-1182 4435,-1182 4435,-1610 4660,-1610 4660,-1585 4750,-1585 4750,-1520 4585,-1520 4545,-1480 4545,-1246
0 on TOP "TOP-0 1" (solid, remove dead copper, pour order 10): 4426,-1311 4426,-1235 4318,-1235 4318,-1311
+15V on TOP "TOP-+15V" (solid, remove dead copper, pour order 22): 4970,-1353 5070,-1353 5070,-1258 5183,-1258 5183,-1585 4970,-1585
+15V on TOP "TOP-+15V 1" (solid, remove dead copper, pour order 23): 5185,-1720 4735,-1720 4735,-1590 4970,-1590 4970,-1580 5185,-1580
0 on TOP "TOP-0 2" (solid, remove dead copper, pour order 26): 4619,-1311 4619,-1009 4490,-1009 4490,-1124 4420,-1124 4420,-992 4434,-978 4741,-978 4741,-1001 4741,-1098 4989,-1098 4989,-1187 4938,-1187 4938,-1239 4871,-1239 4871,-1137 4816,-1137 4786,-1167 4745,-1167 4741,-1171 4741,-1311
+5V on TOP "TOP-+5V" (solid, remove dead copper, pour order 33): -1880,915 -2030,915 -2030,1495 -1910,1495 -1910,1630 -2185,1630 -2185,810 -1880,810
N204300 on TOP "TOP-N204300" (solid, remove dead copper, pour order 6): 4570,-1089 4570,-1143 4574,-1147 4574,-1167 4610,-1167 4610,-1089
N209249 on TOP "TOP-N209249" (solid, remove dead copper, pour order 5): 3740,-924 3740,-978 3744,-982 3744,-1002 3780,-1002 3780,-924
N204715 on TOP "TOP-N204715" (solid, remove dead copper, pour order 3): 4750,-1175 4794,-1175 4821,-1148 4862,-1148 4862,-1188 4803,-1188 4802,-1187 4750,-1187
+12V on TOP "TOP-+12V 2" (solid, remove dead copper, pour order 32): -3945,-1628.33 -3945,-1440 -3570,-1440 -3570,-1980 -3720,-1980 -3720,-1628.33
N209493 on TOP "TOP-N209493" (solid, remove dead copper, pour order 7): 3675,-942 3675,-850 3720,-850 3720,-942
N147166 on TOP "TOP-N147166" (solid, remove dead copper, pour order 17): -4157.5,-1921.67 -4097.5,-1921.67 -4097.5,-1861.67 -3992.5,-1861.67 -3992.5,-2031.67 -4047.5,-2031.67 -4047.5,-2086.67 -4157.5,-2086.67
0 on TOP "TOP-0 3" (solid, remove dead copper, pour order 12): 5057,-1334 5057,-1262 4875,-1262 4875,-1323 4886,-1334
0 on TOP "TOP-0 4" (solid, remove dead copper, pour order 15): 4247,-1198 4247,-1097 3976,-1097 3976,-1198
+12V on TOP "TOP-+12V 3" (solid, remove dead copper, pour order 31): 3780,-1081 3780,-1069 3665,-1069 3665,-1017 3605,-1017 3605,-1156 3505,-1156 3490,-1171 3490,-1366 3605,-1481 4161,-1481 4161,-1399 4161,-1319 4023,-1319 4023,-1399 3699,-1399 3599,-1399 3593,-1393 3593,-1260 3715,-1260 3715,-1081
VIN on TOP "TOP-VIN" (solid, remove dead copper, pour order 34): -4925,-1690 -4615,-1690 -4445,-1860 -4315,-1860 -4315,-1795 -4255,-1795 -4255,-1860 -4165,-1860 -4165,-2095 -4445,-2095 -4925,-2095
N209421 on TOP "TOP-N209421" (solid, remove dead copper, pour order 4): 3920,-1010 3964,-1010 3991,-983 4032,-983 4032,-1023 3973,-1023 3972,-1022 3920,-1022
N209309 on TOP "TOP-N209309" (solid, remove dead copper, pour order 0): 3780,-1049 3742,-1049 3711,-1018 3681,-1018 3681,-1062 3780,-1062
N209373 on TOP "TOP-N209373" (solid, remove dead copper, pour order 1): 4030,-1033 3974,-1033 3970,-1029 3920,-1029 3920,-1041 3962,-1041 3994,-1073 4030,-1073
-15V on TOP "TOP--15V" (solid, remove dead copper, pour order 19): 4023,-1311 4023,-1233 4305,-1233 4305,-1320 4350,-1320 4350,-1485 4170,-1485 4170,-1480 4170,-1311
0 on TOP "TOP-0 5" (solid, remove dead copper, pour order 11): 3602,-1388 3602,-1269 3693,-1269 3693,-1388
N209381 on TOP "TOP-N209381" (solid, remove dead copper, pour order 8): 3620,-966 3717,-966 3725,-974 3725,-993 3742,-1010 3780,-1010 3780,-1022.32 3730.32,-1022.32 3716,-1008 3620,-1008
N148540 on TOP "TOP-N148540" (solid, remove dead copper, pour order 27): -3987.5,-2091.67 -3987.5,-1830.83 -3933.34,-1776.67 -3742.5,-1776.67 -3742.5,-2091.67
0 on TOP "TOP-0 6" (solid, remove dead copper, pour order 25): 3789,-1146 3789,-844 3667,-844 3667,-959 3603,-959 3603,-814 3604,-813 3911,-813 3911,-836 3911,-933 4123,-933 4140,-950 4140,-1022 4108,-1022 4108,-1074 4041,-1074 4041,-972 3986,-972 3956,-1002 3915,-1002 3911,-1006 3911,-1146
-15V on TOP "TOP--15V 1" (solid, remove dead copper, pour order 35): 3440,-1800 4040,-1800 4040,-1610 4170,-1480 4350,-1480 4350,-1800 4860,-1800 4860,-2050 3440,-2050
1 on GND1 "GND1-1" (solid, remove dead copper, pour order 41): -4480,1297 -4480,197 cw(c-4580,197) -4580,97 -5199.96,97 cw(c-5199.96,197) -5299.96,197 -5299.96,1297 cw(c-5199.96,1297) -5199.96,1397 -4580,1397 cw(c-4580,1297)
0 on GND1 "GND1-0" (solid, remove dead copper, pour order 20): 4619,-1149 4619,-1250 4438,-1250 4423,-1235 4318,-1235 4318,-1311 4859,-1311 4882,-1334 4936,-1334 4936,-1250 4741,-1250 4741,-1149
no net on GND1 "GND1-No Net" (solid, remove dead copper, pour order 28): 3789,-984 3789,-1085 3608,-1085 3593,-1070 3488,-1070 3488,-1146 3766,-1146 3643,-1269 3602,-1269 3602,-1388 3693,-1388 3693,-1308 3855,-1146 3953,-1146 4005,-1198 4106,-1198 4106,-1097 3911,-1097 3911,-984
0 on GND1 "GND1-0 1" (solid, remove dead copper, pour order 46): -4245,20 -4245,520 -4345,520 -4345,680 -4245,680 -4245,1430 ccw(c-4345,1430) -4345,1530 -4658.62,1530 cw(c-4658.62,1630) -4758.62,1630 -4758.62,1763.78 cw(c-4537.4,1763.78) -4537.4,1985 2340,1985 cw(c2340,1885) 2440,1885 2440,196.42 ccw(c2540,196.42) 2469.29,125.71 2605.71,-10.71 ccw(c2676.42,60) 2676.42,-40 3318.58,-40 cw(c3318.58,-140) 3389.29,-69.29 4240.71,-920.71 ccw(c4311.42,-850) 4311.42,-950 5199.96,-950 cw(c5199.96,-1050) 5299.96,-1050 5299.96,-1936.89 cw(c5078.74,-1936.89) 5078.74,-2158.11 3564.68,-2158.11 cw(c3564.68,-1936.89) 3343.46,-1936.89 3343.46,-1700.79 ccw(c3092.24,-1700.79) 3092.24,-1449.57 -3092.24,-1449.57 ccw(c-3092.24,-1700.79) -3343.46,-1700.79 -3343.46,-1936.89 cw(c-3564.68,-1936.89) -3564.68,-2158.11 -5214.96,-2158.11 cw(c-5214.96,-2073.11) -5299.96,-2073.11 -5299.96,-180 cw(c-5199.96,-180) -5199.96,-80 -4345,-80 ccw(c-4345,20)
0 on GND2 "GND2-0" (solid, remove dead copper, pour order 45): -4245,20 -4245,520 -4345,520 -4345,680 -4245,680 -4245,1430 ccw(c-4345,1430) -4345,1530 -4658.62,1530 cw(c-4658.62,1630) -4758.62,1630 -4758.62,1763.78 cw(c-4537.4,1763.78) -4537.4,1985 2340,1985 cw(c2340,1885) 2440,1885 2440,196.42 ccw(c2540,196.42) 2469.29,125.71 2605.71,-10.71 ccw(c2676.42,60) 2676.42,-40 3318.58,-40 cw(c3318.58,-140) 3389.29,-69.29 4240.71,-920.71 ccw(c4311.42,-850) 4311.42,-950 5199.96,-950 cw(c5199.96,-1050) 5299.96,-1050 5299.96,-1936.89 cw(c5078.74,-1936.89) 5078.74,-2158.11 3564.68,-2158.11 cw(c3564.68,-1936.89) 3343.46,-1936.89 3343.46,-1700.79 ccw(c3092.24,-1700.79) 3092.24,-1449.57 -3092.24,-1449.57 ccw(c-3092.24,-1700.79) -3343.46,-1700.79 -3343.46,-1936.89 cw(c-3564.68,-1936.89) -3564.68,-2158.11 -5214.96,-2158.11 cw(c-5214.96,-2073.11) -5299.96,-2073.11 -5299.96,-180 cw(c-5199.96,-180) -5199.96,-80 -4345,-80 ccw(c-4345,20)
1 on GND2 "GND2-1" (solid, remove dead copper, pour order 40): -4480,1297 -4480,197 cw(c-4580,197) -4580,97 -5199.96,97 cw(c-5199.96,197) -5299.96,197 -5299.96,1297 cw(c-5199.96,1297) -5199.96,1397 -4580,1397 cw(c-4580,1297)
+3V3 on PWR "PWR-+3V3" (solid, remove dead copper, pour order 44): -4245,20 -4245,520 -4345,520 -4345,680 -4245,680 -4245,1430 ccw(c-4345,1430) -4345,1530 -4658.62,1530 cw(c-4658.62,1630) -4758.62,1630 -4758.62,1763.78 cw(c-4537.4,1763.78) -4537.4,1985 2340,1985 cw(c2340,1885) 2440,1885 2440,196.42 ccw(c2540,196.42) 2469.29,125.71 2605.71,-10.71 ccw(c2676.42,60) 2676.42,-40 3318.58,-40 cw(c3318.58,-140) 3389.29,-69.29 4240.71,-920.71 ccw(c4311.42,-850) 4311.42,-950 5199.96,-950 cw(c5199.96,-1050) 5299.96,-1050 5299.96,-1936.89 cw(c5078.74,-1936.89) 5078.74,-2158.11 3564.68,-2158.11 cw(c3564.68,-1936.89) 3343.46,-1936.89 3343.46,-1700.79 ccw(c3092.24,-1700.79) 3092.24,-1449.57 -3092.24,-1449.57 ccw(c-3092.24,-1700.79) -3343.46,-1700.79 -3343.46,-1936.89 cw(c-3564.68,-1936.89) -3564.68,-2158.11 -5214.96,-2158.11 cw(c-5214.96,-2073.11) -5299.96,-2073.11 -5299.96,-180 cw(c-5199.96,-180) -5199.96,-80 -4345,-80 ccw(c-4345,20)
+5V-ISO on PWR "PWR-+5V-ISO" (solid, remove dead copper, pour order 39): -4480,1297 -4480,197 cw(c-4580,197) -4580,97 -5199.96,97 cw(c-5199.96,197) -5299.96,197 -5299.96,1297 cw(c-5199.96,1297) -5199.96,1397 -4580,1397 cw(c-4580,1297)
+5V on BOTTOM "BOTTOM-+5V" (solid, remove dead copper, pour order 38): -3330,-455 -2185,-455 -2185,915 -1880,915 -1880,810 -2030,810 -2030,310 -1885,310 -1885,210 -2030,210 -2030,-455 -745,-455 -680,-520 -680,-710 -685,-715 -3330,-715
-15V on BOTTOM "BOTTOM--15V" (solid, remove dead copper, pour order 30): -5070,-920 -5095,-895 -5185,-895 -5185,-1035 -4995,-1225 -4625,-1225 -4415,-1015 -4415,-945 -4500,-945 -4700,-1145 -4935,-1145 -5070,-1010
+15V on BOTTOM "BOTTOM-+15V" (solid, remove dead copper, pour order 29): -4470,-930 -4510,-930 -4710,-1130 -4925,-1130 -5040,-1015 -5040,-890 -4920,-890 -4905,-905 -4905,-1005 -4735,-1005 -4590,-860 -4470,-860
+15V on BOTTOM "BOTTOM-+15V 1" (solid, remove dead copper, pour order 42): -4490,-860 -4490,-930 3575,-930 3620,-975 3910,-975 4027.5,-1092.5 4217.5,-1092.5 4680,-1555 4680,-1740 4620,-1800 3440,-1800 3440,-2050 4860,-2050 4860,-1800 4940,-1720 5185,-1720 5185,-1545 5170,-1530 4835,-1530 4165,-860
+12V on BOTTOM "BOTTOM-+12V" (solid, remove dead copper, pour order 43): -3945,-1030.13 3394.33,-1029.33 3860,-1495 4585,-1495 4660,-1570 4660,-1640 3400,-1640 3205,-1445 -3355,-1445 -3475,-1565 -3475,-2035 -3535,-2095 -3945,-2095
-15V on BOTTOM "BOTTOM--15V 1" (solid, remove dead copper, pour order 36): -4480,-945 -4480,-1015 3490,-1015 3960,-1485 4350,-1485 4350,-1320 4165,-1320 4100,-1385 3990,-1385 3550,-945

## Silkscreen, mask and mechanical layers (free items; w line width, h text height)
Top Overlay:
  drawing of 126 lines, arcs and shapes, not listed
  text "VDC-" at 3987,1693.5 h63
  text "Controller V1.2" at -4374,1584 h63
  text "VDC+" at 3987,1293.5 h63
  text "CAUTION" at 3551,950 h63
  text "HIGH" at 3653,862 h63
  text "VC-" at 4082,824.9 h63
  text "VOLTAGE" at 3555,773 h63
  text "VC+" at 4082,529.62 h63
  text "VB-" at 4082,234.34 h63
  text "CAN" at -4713.5,93.5 h63 r90
  text "VB+" at 4082,-60.94 h63
  text "+5V" at -3461.5,-346.5 h63
  text "+3V3" at -2268,-351.5 h63
  text "VA-" at 4082,-356.22 h63
  text "VA+" at 4082,-651.5 h63
  text "GD-U" at -2328,-1051.5 h63
  text "GD-V" at -133,-1051.5 h63
  text "GD-W" at 2077,-1056.5 h63
  text "AUX" at -4728.5,-1563 h63 r90
  text "12V" at -3393.5,-1663 h63 r90
  text "+" at -3615,-1725 h63
  text "-15V" at 3770,-1770 h63
  text "+15V" at 4445,-1770 h63
  text "12V" at -3393.5,-1993 h63 r90
  text "+" at -3615,-2055 h63
  text "POWER" at -4653.5,-2091.5 h63 r90
  text "I-U" at 3563.5,-2131.5 h63
  text "I-V" at 4073.5,-2131.5 h63
  text "I-W" at 4583.5,-2131.5 h63
DESIGN_OUTLINE:
  the board outline again, w1
DIMENSION:
  lines w1: -3015.43,-3022.76 -3026.28,-3011.91 ; -6033,-2023.11 -5983,-2023.11 ; -6033,-2023.11 -6008,-2173.11 ; -6033,-2023.11 -5983,-2023.11 ; -6033,-2023.11 -6008,-2173.11 ; -6033,1850 -5983,1850 ; -6033,1850 -6008,2000 ; -6033,1850 -5983,1850 ; -6033,1850 -6008,2000 ; -6008,-2173.11 -6008,-668.25 -6008,-2173.11 ; -6008,-2173.11 -5983,-2023.11 ; -6008,-2173.11 -5983,-2023.11 ; -6008,2000 -5983,1850 ; -6008,2000 -5983,1850 ; -6008,2000 -6008,-355.75 -6008,2000 ; -5314.96,2327 -202.25,2327 -5314.96,2327 ; -5314.96,2327 -5164.96,2302 ; -5314.96,2327 -5164.96,2352 ; -5314.96,2327 -5164.96,2302 ; -5314.96,2327 -5164.96,2352 ; -5164.96,2302 -5164.96,2352 ; -5164.96,2302 -5164.96,2352 ; -3026.29,-3011.91 -3026.28,-3011.91 ; 5164.96,2302 5164.96,2352 ; 5164.96,2302 5314.96,2327 ; 5164.96,2302 5164.96,2352 ; 5164.96,2302 5314.96,2327 ; 5164.96,2352 5314.96,2327 ; 5164.96,2352 5314.96,2327 ; 5314.96,2327 574.25,2327 5314.96,2327 ; -6108,-2173.11 -4327.43,-2173.11 -6108,-2173.11 ; -6108,2000 -4007.85,2000 -6108,2000 ; -5314.96,1361.15 -5314.96,2427 -5314.96,1361.15 ; 5314.96,1122.41 5314.96,2427 5314.96,1122.41
  text "10.63" at -108.5,2264.5 h125
  text "10.63" at -108.5,2264.5 h125
  text "4.17" at -6240.5,-574.5 h125
  text "4.17" at -6240.5,-574.5 h125
NCLEGEND-1-6:
  circle w1: c6174.5,-550 r25
  circle w1: c6174.5,700 r25
  circle w1: c6174.5,-1800 r12.5
  circle w1: c6174.5,-50 r22.5
  circle w1: c6174.5,-1050 r42.5
  circle w1: c6174.5,-800 r35
  circle w1: c6174.5,-1300 r61.5
  lines w1: 5725,-1675 10685,-1675 ; 5725,-1425 10685,-1425 ; 5725,-1175 10685,-1175 ; 5725,-925 10685,-925 ; 5725,-675 10685,-675 ; 5725,-425 10685,-425 ; 5725,-175 10685,-175 ; 5725,75 10685,75 ; 5725,325 10685,325 ; 5725,575 10685,575 ; 5725,825 10685,825 ; 5725,1075 10685,1075 ; 5725,1325 10685,1325 ; 6135.13,-300 6213.87,-300 ; 6160.5,450 6188.5,450 ; 6174.5,-339.37 6174.5,-260.63 ; 6174.5,436 6174.5,464 ; 6624,-1925 6624,1075 ; 8639,-1925 8639,1075 ; 9910,-1925 9910,1075 ; 5725,-1925 5725,1575 10685,1575 10685,-1925 5725,-1925 ; 6099.5,-1557.5 ccw(c6174.5,-1557.5) 6249.5,-1557.5 6249.5,-1542.5 ccw(c6174.5,-1542.5) 6099.5,-1542.5 6099.5,-1557.5 ; 6149.5,200 6162,175 6187,175 6199.5,200 6187,225 6162,225 6149.5,200
  text "DRILL CHART: TOP to BOTTOM" at 6905,1387.5 h125
  text "ALL UNITS ARE IN MILS" at 7155,1137.5 h125
  text "FIGURE" at 5874.5,887.5 h125
  text "FINISHED_SIZE" at 6981.5,887.5 h125
  text "PLATED" at 8974.5,887.5 h125
  text "QTY" at 10147.5,887.5 h125
  text "13.0" at 7431.5,637.5 h125
  text "PLATED" at 8974.5,637.5 h125
  text "503" at 10147.5,637.5 h125
  text "28.0" at 7431.5,387.5 h125
  text "PLATED" at 8974.5,387.5 h125
  text "26" at 10197.5,387.5 h125
  text "36.0" at 7431.5,137.5 h125
  text "PLATED" at 8974.5,137.5 h125
  text "9" at 10247.5,137.5 h125
  text "45.0" at 7431.5,-112.5 h125
  text "PLATED" at 8974.5,-112.5 h125
  text "168" at 10147.5,-112.5 h125
  text "47.24" at 7381.5,-362.5 h125
  text "PLATED" at 8974.5,-362.5 h125
  text "6" at 10247.5,-362.5 h125
  text "50.0" at 7431.5,-612.5 h125
  text "PLATED" at 8974.5,-612.5 h125
  text "3" at 10247.5,-612.5 h125
  text "70.0" at 7431.5,-862.5 h125
  text "PLATED" at 8974.5,-862.5 h125
  text "2" at 10247.5,-862.5 h125
  text "85.0" at 7431.5,-1112.5 h125
  text "PLATED" at 8974.5,-1112.5 h125
  text "6" at 10247.5,-1112.5 h125
  text "110.0" at 7381.5,-1362.5 h125
  text "PLATED" at 8974.5,-1362.5 h125
  text "2" at 10247.5,-1362.5 h125
  text "130.0" at 7381.5,-1612.5 h125
  text "PLATED" at 8974.5,-1612.5 h125
  text "2" at 10247.5,-1612.5 h125
  text "170.0" at 7381.5,-1862.5 h125
  text "NON-PLATED" at 8774.5,-1862.5 h125
  text "7" at 10247.5,-1862.5 h125
ASSEMBLY_NOTES:
  drawing of 147 lines, arcs and shapes, not listed
  text "Connector Housing" at -7185,195 h75
  text "Connector Housing" at -6735,-1495 h75
  text "Connector Housing" at -6580,-1920 h75
ASSEMBLY_TOP:
  drawing of 210 lines, arcs and shapes, not listed
XSECTION_CHART:
  region: 5620,3462.56 6220,3462.56 6220,3507.35 5620,3507.35
  region: 5620,4064.14 6220,4064.14 6220,4108.93 5620,4108.93
  dashed: 5820,4108.93 5820,4064.14 5845,4064.14 5845,2169.73 5820,2169.73 5820,2124.94 5970,2124.94 5970,2169.73 5945,2169.73 5945,4064.14 5970,4064.14 5970,4108.93
  region: 5620,2726.57 6220,2726.57 6220,2771.36 5620,2771.36
  region: 5620,2425.78 6220,2425.78 6220,2470.57 5620,2470.57
  region: 5620,3763.35 6220,3763.35 6220,3808.14 5620,3808.14
  region: 5620,2124.99 6220,2124.99 6220,2169.78 5620,2169.78
  lines w1: 5620,2169.78 5620,2425.78 6220,2425.78 6220,2169.78 5620,2169.78 ; 5620,2470.57 5620,2726.57 6220,2726.57 6220,2470.57 5620,2470.57 ; 5620,2771.36 5620,3462.56 6220,3462.56 6220,2771.36 5620,2771.36 ; 5620,3507.35 5620,3763.35 6220,3763.35 6220,3507.35 5620,3507.35 ; 5620,3808.14 5620,4064.14 6220,4064.14 6220,3808.14 5620,3808.14
  text "1-6" at 5895,4133.93 h25 r90
  text "*  SURFACE - 0 MIL" at 6220,4117.26 h25
  text "L1 TOP CONDUCTOR - 1.4 MIL" at 6220,4075.6 h25
  text "*  DIELECTRIC - 8 MIL" at 6220,3936.14 h25
  text "L2 GND1 CONDUCTOR - 1.4 MIL" at 6220,3774.81 h25
  text "*  DIELECTRIC - 8 MIL" at 6220,3635.35 h25
  text "L3 LAYER3 CONDUCTOR - 1.4 MIL" at 6220,3474.02 h25
  text "*  DIELECTRIC - 21.6 MIL" at 6220,3116.96 h25
  text "L4 PWR CONDUCTOR - 1.4 MIL" at 6220,2738.03 h25
  text "*  DIELECTRIC - 8 MIL" at 6220,2598.57 h25
  text "L5 GND2 CONDUCTOR - 1.4 MIL" at 6220,2437.24 h25
  text "*  DIELECTRIC - 8 MIL" at 6220,2297.78 h25
  text "L6 BOTTOM CONDUCTOR - 1.4 MIL" at 6220,2136.45 h25
  text "*  SURFACE - 0 MIL" at 6220,2091.66 h25
  text "___________________________" at 5650,2033.33 h25
  text "DESIGN CROSS SECTION CHART" at 5660,2033.33 h25
  text "TOTAL THICKNESS 62 MIL" at 5700,1988.33 h25
DRAWING_ORIGIN:
  lines w1: -25,0 25,0 ; 0,-25 0,25
ASSEMBLY_DETAIL:
  drawing of 67360 lines, arcs and shapes, not listed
